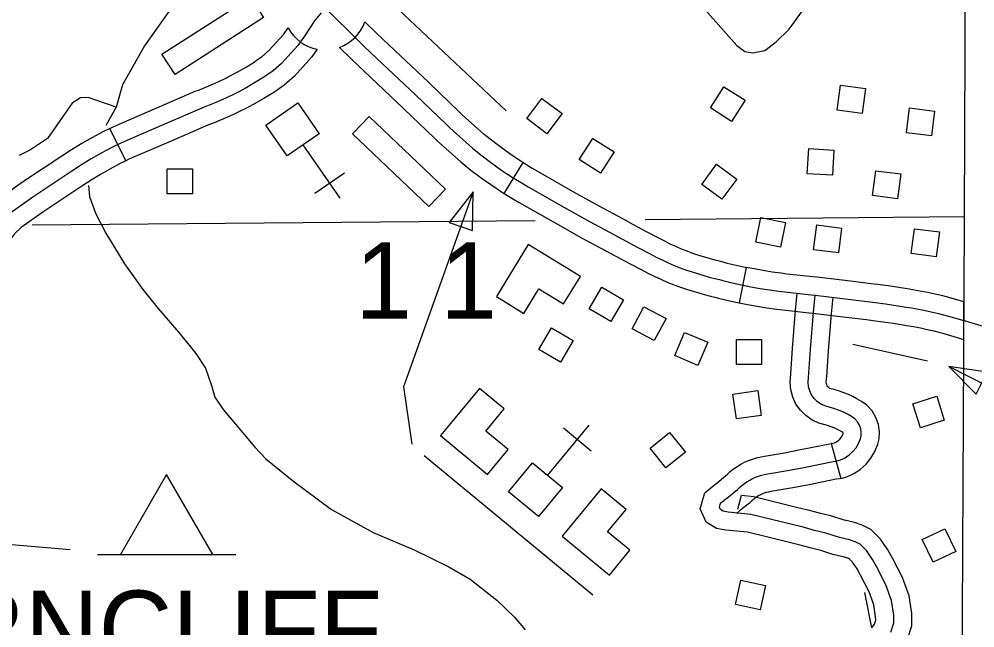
# Model space of a CAD drawing. Extents: x -19 to 366, y -4 to 359.
# Drawn here: x 138.656 to 139.407, y 192.696 to 193.174 of the extents above; entities that cross this region are included whole.
import ezdxf

# ---------------------------------------------------------------- set-up
doc = ezdxf.new("R2010")
doc.units = 0
for name, color, linetype in [('Level 31', 7, 'Continuous'), ('Level 35', 7, 'Continuous'), ('Level 38', 7, 'Continuous'), ('Level 5', 7, 'Continuous'), ('Level 56', 7, 'Continuous'), ('Level 57', 7, 'Continuous'), ('Level 58', 7, 'Continuous'), ('Level 60', 7, 'Continuous'), ('Level 63', 7, 'Continuous')]:
    doc.layers.add(name, color=color, linetype=linetype)

msp = doc.modelspace()

# ---------------------------------------------------------------- linework, layer by layer
at = {"layer": 'Level 31'}
for p, q in [((138.73964, 193.06271), (138.72716, 193.08823)), ((139.0372, 193.03717), (139.05211, 193.06135)), ((139.05211, 193.06135), (139.05211, 193.06134)), ((139.22763, 192.97894), (139.22204, 192.95108)), ((139.39872, 192.92236), (139.39886, 192.95186)), ((139.29443, 192.84042), (139.30204, 192.81305))]:
    msp.add_line(p, q, dxfattribs=at)
for points in [[(138.89643, 193.18303), (138.90191, 193.17751), (138.91779, 193.1619), (138.92694, 193.15292), (138.93713, 193.14329), (138.96765, 193.11448), (138.99204, 193.09097)], [(138.89326, 193.17904), (138.888, 193.17272), (138.88014, 193.16077), (138.87501, 193.15347), (138.86224, 193.13932), (138.85562, 193.13349), (138.85061, 193.13004), (138.84826, 193.12846), (138.84103, 193.12395), (138.83363, 193.1197), (138.82608, 193.11571), (138.81839, 193.112), (138.81059, 193.10856), (138.80268, 193.1054), (138.79956, 193.10425), (138.76966, 193.09128), (138.73625, 193.07687), (138.72817, 193.07292), (138.72024, 193.0687), (138.71242, 193.06423), (138.70477, 193.0595), (138.69727, 193.05453), (138.6665, 193.03418), (138.64677, 193.01996)], [(138.97833, 193.12391), (138.97745, 193.12476), (138.94689, 193.15361), (138.9368, 193.16315), (138.92771, 193.17207)], [(138.81894, 193.12804), (138.81967, 193.12839), (138.82678, 193.13214), (138.83373, 193.13614), (138.84053, 193.14038), (138.84261, 193.14178), (138.84687, 193.14471), (138.85224, 193.14944), (138.86389, 193.16235), (138.86731, 193.16722)], [(138.89026, 193.15047), (138.88613, 193.1446), (138.87224, 193.1292), (138.86437, 193.12227), (138.85861, 193.1183), (138.856, 193.11654), (138.84833, 193.11176), (138.84048, 193.10725), (138.83248, 193.10303), (138.83131, 193.10246)], [(138.90773, 193.15187), (138.91709, 193.14269), (138.92738, 193.13296), (138.95784, 193.1042), (138.95861, 193.10346)], [(138.72716, 193.08823), (138.73031, 193.08977), (138.76402, 193.10432), (138.79427, 193.11743), (138.79758, 193.11866), (138.80509, 193.12166), (138.81244, 193.1249), (138.81894, 193.12804)], [(139.05211, 193.06134), (139.05126, 193.06187), (139.04352, 193.06697), (139.03594, 193.07231), (139.02854, 193.07786), (139.02144, 193.08354), (139.00416, 193.09899), (139.00191, 193.10118), (138.97833, 193.12391)], [(138.83131, 193.10246), (138.82435, 193.0991), (138.81609, 193.09546), (138.80778, 193.09214), (138.80485, 193.09106), (138.7753, 193.07825), (138.74218, 193.06396), (138.73964, 193.06271)], [(138.95861, 193.10346), (138.98216, 193.08076), (138.98479, 193.07821), (139.00309, 193.06185), (139.01113, 193.05541), (139.01924, 193.04932), (139.02753, 193.04349), (139.03598, 193.03792), (139.0372, 193.03717)], [(138.99204, 193.09097), (138.99448, 193.0886), (139.01227, 193.0727), (139.01984, 193.06664), (139.02759, 193.06081), (139.03553, 193.05523), (139.04362, 193.04989), (139.05187, 193.0448), (139.05624, 193.04226)], [(138.72716, 193.08823), (138.72171, 193.08557), (138.71338, 193.08114), (138.70516, 193.07644), (138.69711, 193.07146), (138.68943, 193.06637), (138.65842, 193.04587), (138.64091, 193.03325)], [(138.73964, 193.06271), (138.73463, 193.06026), (138.72711, 193.05626), (138.71968, 193.05201), (138.71243, 193.04754), (138.70511, 193.04268), (138.67457, 193.02249), (138.65752, 193.0102)], [(139.05211, 193.06135), (139.05918, 193.05699), (139.06334, 193.05456), (139.09124, 193.03861), (139.11171, 193.02723), (139.13026, 193.01727), (139.13859, 193.01274)], [(139.0372, 193.03717), (139.04456, 193.03262), (139.04913, 193.02996), (139.07728, 193.01386), (139.09809, 193.0023), (139.11676, 192.99227), (139.12503, 192.98778)], [(139.05624, 193.04226), (139.08426, 193.02623), (139.1049, 193.01476), (139.12351, 193.00477), (139.14238, 192.99451), (139.15215, 192.98956), (139.15677, 192.98711), (139.16143, 192.98479), (139.16614, 192.9826), (139.17094, 192.98054), (139.17578, 192.97861), (139.18067, 192.97682), (139.185, 192.97536), (139.19931, 192.97104), (139.20291, 192.97022), (139.20652, 192.96932), (139.20922, 192.96859), (139.21649, 192.96683), (139.22381, 192.96522), (139.23115, 192.96374), (139.23851, 192.96242), (139.24591, 192.96124), (139.25333, 192.96021), (139.25806, 192.95963), (139.27864, 192.95743), (139.28173, 192.95707)], [(138.65752, 193.0102), (138.656, 193.0091), (138.65387, 193.00698), (138.65145, 193.00422), (138.6492, 193.00128), (138.64712, 192.9982), (138.64528, 192.99504), (138.64359, 192.99157), (138.62794, 192.95651), (138.62763, 192.9551), (138.62733, 192.95286), (138.62723, 192.95058), (138.62731, 192.9483), (138.6276, 192.94605), (138.62806, 192.94384), (138.62875, 192.94159), (138.62945, 192.93976), (138.63027, 192.9377)], [(139.13859, 193.01274), (139.14899, 193.00709), (139.15869, 193.00217), (139.16326, 192.99975), (139.1676, 192.99759), (139.17194, 192.99556), (139.17637, 192.99366), (139.18085, 192.99188), (139.18538, 192.99022), (139.18932, 192.98889), (139.20295, 192.98478), (139.20623, 192.98403), (139.21009, 192.98307), (139.21273, 192.98236), (139.21969, 192.98067), (139.22674, 192.97912), (139.22763, 192.97894)], [(139.12503, 192.98778), (139.13578, 192.98193), (139.14561, 192.97695), (139.15028, 192.97448), (139.15527, 192.97199), (139.16034, 192.96963), (139.16551, 192.96741), (139.17071, 192.96534), (139.17595, 192.96342), (139.18068, 192.96183), (139.19567, 192.9573), (139.1996, 192.9564), (139.20295, 192.95557), (139.2057, 192.95483), (139.21329, 192.95299), (139.22088, 192.95132), (139.22204, 192.95108)], [(139.32569, 192.96616), (139.31163, 192.96789), (139.28336, 192.97118), (139.28021, 192.97155), (139.25968, 192.97374), (139.25517, 192.97429), (139.248, 192.97529), (139.24089, 192.97642), (139.23381, 192.9777), (139.22763, 192.97894)], [(139.39886, 192.95186), (139.39057, 192.95423), (139.38226, 192.95651), (139.37621, 192.95795), (139.37021, 192.95923), (139.36416, 192.96037), (139.35837, 192.96132), (139.35592, 192.96176), (139.34759, 192.96316), (139.33918, 192.96442), (139.33085, 192.96552), (139.32569, 192.96616)], [(139.26257, 192.89519), (139.26403, 192.91543), (139.26624, 192.94499), (139.26759, 192.95848)], [(139.30865, 192.83149), (139.31156, 192.83411), (139.31405, 192.83714), (139.31603, 192.84053), (139.31746, 192.84418), (139.31792, 192.84618), (139.31809, 192.84919), (139.31767, 192.85218), (139.31666, 192.85502), (139.31512, 192.85761), (139.31306, 192.85985), (139.31052, 192.86167), (139.30787, 192.8632), (139.30513, 192.86461), (139.30234, 192.8659), (139.29946, 192.86705), (139.29657, 192.86806), (139.2936, 192.86894), (139.28952, 192.87003), (139.28638, 192.87149), (139.28352, 192.87346), (139.28106, 192.87589), (139.27905, 192.87872), (139.27756, 192.88185), (139.27666, 192.88519), (139.27634, 192.88864), (139.2782, 192.91438), (139.2804, 192.94375), (139.28173, 192.95707)], [(139.28173, 192.95707), (139.30994, 192.95378), (139.32905, 192.95143), (139.33721, 192.95035), (139.34537, 192.94913), (139.35348, 192.94777), (139.35596, 192.94732), (139.3617, 192.94638), (139.36741, 192.9453), (139.37309, 192.94409), (139.37874, 192.94274), (139.38674, 192.94055), (139.39879, 192.93711)], [(139.29091, 192.89314), (139.29236, 192.91334), (139.29455, 192.94251), (139.29586, 192.95566)], [(139.22204, 192.95108), (139.22849, 192.94979), (139.23613, 192.94841), (139.24381, 192.94719), (139.25149, 192.94612), (139.25644, 192.94552), (139.27706, 192.94331), (139.28009, 192.94296), (139.30825, 192.93968), (139.32222, 192.93796)], [(139.32222, 192.93796), (139.32725, 192.93734), (139.33523, 192.93629), (139.34314, 192.93511), (139.35104, 192.93378), (139.35354, 192.93332), (139.35923, 192.93239), (139.36461, 192.93138), (139.36996, 192.93023), (139.37522, 192.92898), (139.38291, 192.92687), (139.39872, 192.92236)], [(139.59444, 192.90845), (139.58974, 192.9086), (139.57805, 192.90905), (139.56749, 192.90925), (139.53861, 192.91018), (139.51149, 192.91113), (139.50449, 192.91144), (139.49751, 192.91189), (139.49053, 192.91249), (139.48188, 192.9135), (139.47638, 192.91444), (139.4709, 192.91552), (139.46544, 192.91675), (139.46003, 192.91811), (139.45465, 192.91962), (139.43691, 192.92517), (139.42555, 192.92891), (139.41412, 192.93252), (139.40267, 192.93599), (139.39879, 192.93711)], [(139.29442, 192.84042), (139.29692, 192.84112), (139.29851, 192.84184), (139.29997, 192.84279), (139.30125, 192.84394), (139.30236, 192.84529), (139.30321, 192.84675), (139.30382, 192.84829), (139.30383, 192.84859), (139.30381, 192.84878), (139.30375, 192.84895), (139.30367, 192.84908), (139.3036, 192.84915), (139.30281, 192.84972), (139.30106, 192.85073), (139.2989, 192.85184), (139.29673, 192.85284), (139.29447, 192.85374), (139.29219, 192.85454), (139.28975, 192.85527), (139.28467, 192.85663), (139.27931, 192.8591), (139.27442, 192.86248), (139.27019, 192.86666), (139.26676, 192.87151), (139.26419, 192.8769), (139.26263, 192.88266), (139.26209, 192.8885), (139.26257, 192.89519)], [(139.30204, 192.81305), (139.30664, 192.81433), (139.31219, 192.81685), (139.31734, 192.82019), (139.32186, 192.82427), (139.32574, 192.829), (139.32885, 192.83431), (139.33107, 192.83997), (139.33204, 192.84416), (139.33235, 192.84979), (139.33154, 192.85558), (139.32958, 192.86109), (139.32657, 192.86615), (139.32252, 192.87054), (139.31823, 192.87362), (139.31468, 192.87567), (139.31135, 192.87739), (139.30795, 192.87895), (139.30445, 192.88035), (139.30094, 192.88158), (139.29746, 192.88261), (139.29437, 192.88344), (139.29344, 192.88387), (139.29262, 192.88444), (139.29192, 192.88512), (139.29135, 192.88593), (139.29094, 192.8868), (139.29069, 192.88772), (139.29059, 192.88878), (139.29091, 192.89314)], [(139.19351, 192.79641), (139.19499, 192.80179), (139.20127, 192.80696), (139.20474, 192.80972), (139.21136, 192.81499), (139.21262, 192.81623), (139.21509, 192.81843), (139.21771, 192.82049), (139.22047, 192.82241), (139.22337, 192.82416), (139.22635, 192.82573), (139.22942, 192.82711), (139.23255, 192.8283), (139.23576, 192.8293), (139.23901, 192.83012), (139.24204, 192.83067), (139.2576, 192.83327), (139.27031, 192.8357), (139.29347, 192.84034), (139.29496, 192.84057), (139.29443, 192.84042)], [(139.34125, 192.69221), (139.34371, 192.69951), (139.34359, 192.7056), (139.34185, 192.71713), (139.33734, 192.72948), (139.33009, 192.7438), (139.32698, 192.74941), (139.3223, 192.7563), (139.31727, 192.76134), (139.31342, 192.76326), (139.30878, 192.76474), (139.30093, 192.76666), (139.2901, 192.77016), (139.28132, 192.77216), (139.27249, 192.77467), (139.26387, 192.77673), (139.23116, 192.7848), (139.21334, 192.78659), (139.20944, 192.78724), (139.20732, 192.78854), (139.20655, 192.79025), (139.2075, 192.79369), (139.2102, 192.79592), (139.21358, 192.7986), (139.22079, 192.80434), (139.22234, 192.80586), (139.2242, 192.80753), (139.22617, 192.80907), (139.22821, 192.8105), (139.23035, 192.81179), (139.23257, 192.81295), (139.23486, 192.81398), (139.2372, 192.81487), (139.23959, 192.81562), (139.24201, 192.81622), (139.24449, 192.81668), (139.26011, 192.81929), (139.27304, 192.82176), (139.29597, 192.82635), (139.29797, 192.82666), (139.30178, 192.82772), (139.30535, 192.82934), (139.30865, 192.83149)], [(139.30204, 192.81305), (139.30099, 192.81276), (139.29847, 192.81236), (139.27577, 192.80782), (139.26262, 192.8053), (139.24694, 192.80269), (139.24501, 192.80233), (139.24343, 192.80194), (139.24184, 192.80144), (139.2403, 192.80086), (139.23879, 192.80018), (139.23734, 192.79941), (139.23596, 192.79858), (139.23463, 192.79765), (139.23332, 192.79662), (139.23205, 192.7955), (139.23023, 192.7937), (139.22241, 192.78748), (139.21999, 192.78556)], [(139.29578, 192.7534), (139.28633, 192.75645), (139.2778, 192.75839), (139.26889, 192.76092), (139.26052, 192.76293), (139.22873, 192.77077), (139.21146, 192.7725), (139.20436, 192.77369), (139.19617, 192.77873), (139.19149, 192.78907), (139.19351, 192.79642)], [(139.2209, 192.78888), (139.22391, 192.7998), (139.23358, 192.79883), (139.26723, 192.79054), (139.27608, 192.78841), (139.28485, 192.78593), (139.29387, 192.78387), (139.3045, 192.78043)], [(139.35008, 192.67984), (139.35411, 192.6859), (139.35795, 192.69731), (139.35778, 192.70679), (139.35568, 192.72066), (139.35039, 192.73515), (139.34264, 192.75045), (139.33909, 192.75686), (139.3333, 192.76538), (139.32569, 192.77302), (139.31879, 192.77645), (139.31264, 192.77842), (139.3048, 192.78034), (139.30451, 192.78043)], [(139.32643, 192.69559), (139.32839, 192.69852), (139.32946, 192.70171), (139.32941, 192.7044), (139.32802, 192.7136), (139.32428, 192.72382), (139.31753, 192.73715), (139.31487, 192.74196), (139.3113, 192.74721), (139.30885, 192.74966), (139.30806, 192.75006), (139.30493, 192.75106), (139.29706, 192.75298), (139.29578, 192.7534)]]:
    msp.add_lwpolyline(points, dxfattribs=at)
for centre, start, end in [((138.89643, 193.18304), 289.92578, 340.67869), ((138.89643, 193.18303), 208.50795, 259.27125)]:
    msp.add_arc(centre, 0.03314, start, end, dxfattribs=at)
at = {"layer": 'Level 35'}
for points in [[(139.18911, 193.18852), (139.22033, 193.15338), (139.22646, 193.14855), (139.2329, 193.14752), (139.24231, 193.14958), (139.25126, 193.15618), (139.26129, 193.16622), (139.28564, 193.20003), (139.33685, 193.25289), (139.3622, 193.27305), (139.37695, 193.29379), (139.39838, 193.32148), (139.40815, 193.34631)], [(138.82545, 193.23363), (138.82008, 193.22616), (138.81067, 193.21778), (138.8054, 193.21055), (138.7808, 193.1923), (138.77479, 193.18203), (138.75451, 193.15322), (138.73705, 193.12234), (138.73212, 193.10481)], [(138.73212, 193.10481), (138.71022, 193.11239), (138.70398, 193.11233), (138.69751, 193.10803), (138.67805, 193.08031), (138.66465, 193.07142), (138.6558, 193.06691)], [(138.73212, 193.10481), (138.72397, 193.09059)], [(138.71029, 193.04325), (138.71121, 193.03468), (138.71585, 193.0217), (138.72396, 193.00596), (138.73868, 192.98182), (138.75313, 192.96148), (138.76518, 192.94658), (138.78284, 192.9263), (138.79471, 192.9114), (138.80234, 192.89981), (138.807, 192.88607), (138.80967, 192.87703), (138.81632, 192.86713), (138.84118, 192.83772), (138.84989, 192.82843), (138.87184, 192.81053), (138.90144, 192.78862), (138.93435, 192.77058), (138.96659, 192.75707), (138.99373, 192.74345), (139.01039, 192.73396), (139.03155, 192.71736), (139.04546, 192.70402), (139.05381, 192.69396)]]:
    msp.add_lwpolyline(points, dxfattribs=at)
at = {"layer": 'Level 38'}
msp.add_lwpolyline([(139.32643, 192.6956), (139.32086, 192.72345)], dxfattribs=at)
at = {"layer": 'Level 5'}
for points in [[(139.0616, 193.01567), (138.66601, 193.01223)], [(139.39918, 193.01861), (139.14815, 193.01642)]]:
    msp.add_lwpolyline(points, dxfattribs=at)
at = {"layer": 'Level 56'}
for points in [[(138.77845, 193.13053), (138.76816, 193.14644), (138.83775, 193.19143), (138.84803, 193.17552)], [(139.19949, 193.10436), (139.21011, 193.12097), (139.22677, 193.11031), (139.21615, 193.09371)], [(139.29919, 193.10254), (139.30173, 193.12209), (139.32134, 193.11954), (139.3188, 193.09999)], [(139.0551, 193.09587), (139.06691, 193.11165), (139.08274, 193.09981), (139.07093, 193.08402)], [(139.3536, 193.08481), (139.35614, 193.10436), (139.37575, 193.10181), (139.37321, 193.08226)], [(138.91808, 193.08398), (138.93114, 193.0977), (138.99114, 193.04055), (138.97808, 193.02684)], [(139.09636, 193.06371), (139.10698, 193.08032), (139.12364, 193.06967), (139.11302, 193.05306)], [(139.27567, 193.0526), (139.27677, 193.07229), (139.29652, 193.07118), (139.29542, 193.0515)], [(139.22018, 193.04836), (139.20851, 193.03248), (139.19258, 193.04419), (139.20425, 193.06007)], [(138.77236, 193.03671), (138.77236, 193.05642), (138.79213, 193.05642), (138.79213, 193.03671)], [(139.32703, 193.03542), (139.32957, 193.05497), (139.34918, 193.05243), (139.34664, 193.03288)], [(139.2351, 192.99884), (139.23906, 193.01815), (139.25843, 193.01417), (139.25447, 192.99486)], [(139.2805, 192.99284), (139.28304, 193.01239), (139.30265, 193.00985), (139.30011, 192.9903)], [(139.3574, 192.98984), (139.35994, 193.00939), (139.37955, 193.00684), (139.37701, 192.98729)], [(139.10403, 192.94643), (139.11397, 192.96346), (139.13104, 192.95349), (139.1211, 192.93647)], [(139.13789, 192.9307), (139.1472, 192.94808), (139.16463, 192.93874), (139.15532, 192.92136)], [(139.0744, 192.9315), (139.09146, 192.92161), (139.08154, 192.9045), (139.06449, 192.91439)], [(139.19737, 192.92012), (139.18967, 192.90197), (139.17147, 192.90969), (139.17916, 192.92784)], [(139.21992, 192.90265), (139.21992, 192.92237), (139.23969, 192.92237), (139.23969, 192.90265)], [(139.40833, 192.87936), (139.41707, 192.89659), (139.38685, 192.90108)], [(139.21987, 192.85981), (139.21713, 192.87933), (139.23671, 192.88208), (139.23945, 192.86256)], [(139.37741, 192.87765), (139.38341, 192.85887), (139.36458, 192.85285), (139.35857, 192.87163)], [(139.17977, 192.83384), (139.16448, 192.8214), (139.152, 192.83673), (139.16729, 192.84918)], [(139.39235, 192.75564), (139.37455, 192.74717), (139.36606, 192.76502), (139.38386, 192.77349)], [(139.2428, 192.72893), (139.23857, 192.70968), (139.21926, 192.71393), (139.22349, 192.73318)]]:
    msp.add_lwpolyline(points, close=True, dxfattribs=at)
for points in [[(139.3115, 192.91862), (139.37021, 192.90547)], [(139.4736, 192.82567), (139.45082, 192.86864), (139.38685, 192.90108)]]:
    msp.add_lwpolyline(points, dxfattribs=at)
at = {"layer": 'Level 57'}
for p, q in [((138.90818, 193.03334), (138.87914, 193.07525)), ((138.91177, 193.0531), (138.88841, 193.03692)), ((139.10385, 192.85487), (139.07139, 192.81555)), ((139.08386, 192.85296), (139.10577, 192.83488)), ((138.71748, 192.7534), (138.82614, 192.7534))]:
    msp.add_line(p, q, dxfattribs=at)
for points in [[(138.95425, 193.1817), (139.03889, 193.1021)], [(139.01292, 193.03839), (138.95813, 192.8852), (138.96458, 192.84004)], [(138.97423, 192.83111), (139.10708, 192.72144)], [(138.56115, 192.82369), (138.60671, 192.76481), (138.69592, 192.75721)]]:
    msp.add_lwpolyline(points, dxfattribs=at)
for points in [[(138.87495, 193.1083), (138.89178, 193.08401), (138.86658, 193.06656), (138.84976, 193.09085)], [(138.99407, 193.01436), (139.01226, 193.00785), (139.01292, 193.03839)], [(139.04072, 192.80255), (139.05953, 192.82534), (139.08317, 192.80583), (139.06435, 192.78304)], [(138.73559, 192.7534), (138.80803, 192.7534), (138.77181, 192.81614)]]:
    msp.add_lwpolyline(points, close=True, dxfattribs=at)
at = {"layer": 'Level 58'}
for points in [[(139.05625, 192.99706), (139.03111, 192.95605), (139.05274, 192.94278), (139.06464, 192.96219), (139.08402, 192.95031), (139.09727, 192.97192)], [(138.98716, 192.84677), (139.02426, 192.81614), (139.04042, 192.83571), (139.02286, 192.8502), (139.03733, 192.86773), (139.01779, 192.88386)], [(139.0829, 192.76772), (139.12, 192.73709), (139.13616, 192.75667), (139.11861, 192.77116), (139.13308, 192.78869), (139.11353, 192.80482)]]:
    msp.add_lwpolyline(points, close=True, dxfattribs=at)
at = {"layer": 'Level 60'}
for points in [[(146.77834, 1.69699), (146.57878, 10.31313), (146.37852, 18.92942), (146.17757, 27.54584), (145.97591, 36.16241), (145.77356, 44.77911), (145.57052, 53.39596), (145.36679, 62.01295), (145.16236, 70.63008), (144.95724, 79.24735), (144.75142, 87.86477), (144.54492, 96.48232), (144.33773, 105.10002), (144.12986, 113.71787), (143.92129, 122.33585), (143.71204, 130.95398), (143.5021, 139.57225), (143.29148, 148.19067), (143.08018, 156.80923), (142.8682, 165.42794), (142.65553, 174.04679), (142.44218, 182.66579), (142.22816, 191.28493), (142.01345, 199.90421), (141.79807, 208.52365), (141.58202, 217.14322), (141.36528, 225.76295), (141.14788, 234.38282), (140.9298, 243.00284), (140.71105, 251.623), (140.49162, 260.24332), (140.27153, 268.86377), (140.05077, 277.48438), (139.82934, 286.10514), (139.60724, 294.72604), (139.38447, 303.34709), (139.16105, 311.96829), (138.93695, 320.58964), (138.7122, 329.21114), (138.48678, 337.83278), (138.2607, 346.45458)], [(139.44064, 1.53154), (139.25106, 10.14733), (139.06082, 18.76327), (138.86992, 27.37935), (138.67836, 35.99557), (138.48613, 44.61194), (138.29325, 53.22845), (138.09971, 61.84511), (137.9055, 70.46191), (137.71065, 79.07885), (137.51513, 87.69595), (137.31896, 96.31318), (137.12214, 104.93057), (136.92466, 113.54809), (136.72653, 122.16577), (136.52775, 130.78359), (136.32832, 139.40156), (136.12824, 148.01968), (135.9275, 156.63794), (135.72612, 165.25636), (135.5241, 173.87492), (135.32143, 182.49362), (135.11811, 191.11248), (134.91415, 199.73149), (134.70954, 208.35064), (134.50429, 216.96995), (134.2984, 225.5894), (134.09187, 234.209), (133.8847, 242.82876), (133.6769, 251.44866), (133.46845, 260.06872), (133.25937, 268.68892), (133.04965, 277.30928), (132.8393, 285.92978), (132.62831, 294.55044), (132.41669, 303.17125), (132.20444, 311.79221), (131.99156, 320.41333), (131.77805, 329.0346), (131.56391, 337.65601), (131.34914, 346.27759)], [(0, 189.51617), (7.11214, 189.52059), (14.22427, 189.53386), (21.33637, 189.55597), (28.44845, 189.58693), (35.56048, 189.62672), (42.67245, 189.67537), (49.78436, 189.73285), (56.89619, 189.79918), (64.00793, 189.87436), (71.11958, 189.95838), (78.23111, 190.05124), (85.34253, 190.15294), (92.45381, 190.26349), (99.56495, 190.38288), (106.67593, 190.51112), (113.78675, 190.6482), (120.89739, 190.79412), (128.00785, 190.94888), (135.11811, 191.11248), (142.22816, 191.28493), (149.33799, 191.46621), (156.44759, 191.65634), (163.55694, 191.85531), (170.66605, 192.06312), (177.77489, 192.27977), (184.88345, 192.50526), (191.99173, 192.73959), (199.09971, 192.98276), (206.20739, 193.23477), (213.31474, 193.49561), (220.42177, 193.7653), (227.52845, 194.04382), (234.63479, 194.33118), (241.74076, 194.62738), (248.84635, 194.93241), (255.95157, 195.24628), (263.05638, 195.56898), (270.16079, 195.90052), (277.26478, 196.24089), (284.36834, 196.5901), (291.47147, 196.94814), (298.57414, 197.31501), (305.67635, 197.69072), (312.77809, 198.07525), (319.87934, 198.46862), (326.9801, 198.87082), (334.08035, 199.28185), (341.18009, 199.7017)]]:
    msp.add_spline(points, degree=3, dxfattribs=at)
at = {"layer": 'Level 63'}
msp.add_lwpolyline([(139.39691, 192.55137), (139.39916, 193.01408), (139.39918, 193.01861), (139.40311, 194.0054), (139.40283, 194.02364), (139.40489, 195.00522), (139.40486, 195.01798), (139.40149, 196.00809), (139.40143, 196.02666), (139.39674, 197.00568), (139.39669, 197.01653), (139.39179, 198.03814)], dxfattribs=at)

# ---------------------------------------------------------------- texts
at = {"layer": 'Level 56'}
msp.add_text('1 1', height=0.06, dxfattribs=at).set_placement((138.92009, 192.93868))
at = {"layer": 'Level 57'}
msp.add_text('FERNCLIFF', height=0.06, dxfattribs=at).set_placement((138.49993, 192.66491))

doc.saveas('drawing.dxf')
